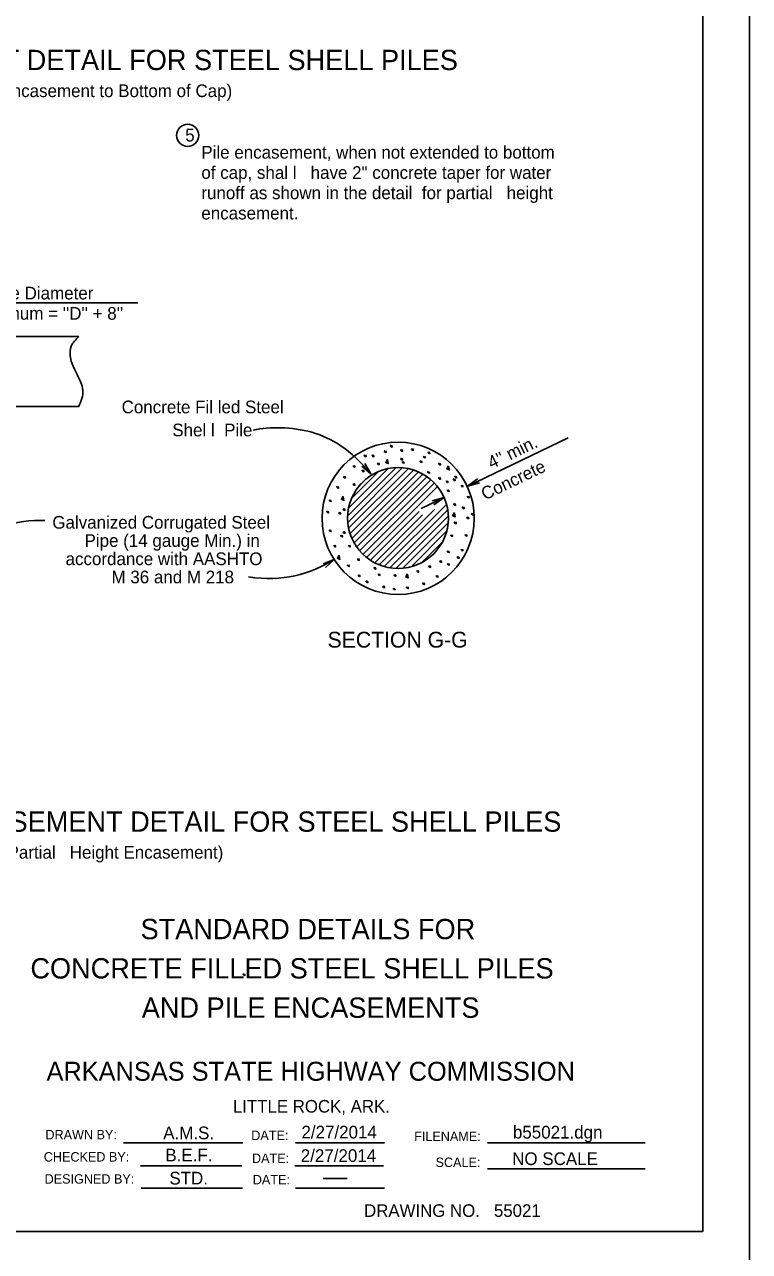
# Model space of a CAD drawing. Extents: x 1053 to 1311, y 5085 to 5337.
# Drawn here: x 1193.9 to 1232, y 5199.9 to 5264.4 of the extents above; entities that cross this region are included whole.
import ezdxf

# ---------------------------------------------------------------- set-up
doc = ezdxf.new("R2010")
doc.units = 0
for name, color, linetype in [('1', 7, 'Continuous'), ('2', 7, 'Continuous'), ('7', 7, 'Continuous'), ('9', 7, 'Continuous'), ('B_No_Plot', 7, 'Continuous')]:
    doc.layers.add(name, color=color, linetype=linetype)

msp = doc.modelspace()

# ---------------------------------------------------------------- linework, layer by layer
at = {"layer": '1'}
for p, q in [((1229.529, 5200.971), (1229.529, 5310.539)), ((1183.514, 5248.033), (1196.697, 5248.033)), ((1183.514, 5244.36), (1196.697, 5244.36)), ((1217.131, 5240.157), (1222.442, 5242.71)), ((1210.846, 5238.615), (1213.369, 5241.138)), ((1210.852, 5238.267), (1213.717, 5241.133)), ((1210.893, 5239.016), (1212.969, 5241.091)), ((1210.895, 5237.957), (1214.027, 5241.089)), ((1210.969, 5237.677), (1214.308, 5241.016)), ((1211.053, 5239.529), (1212.456, 5240.932)), ((1211.066, 5237.421), (1214.563, 5240.918)), ((1211.185, 5237.186), (1214.798, 5240.799)), ((1211.31, 5236.957), (1215.014, 5240.662)), ((1211.503, 5236.797), (1215.213, 5240.507)), ((1211.672, 5236.612), (1215.395, 5240.335)), ((1211.838, 5236.425), (1215.56, 5240.147)), ((1217.145, 5240.171), (1217.679, 5240.555)), ((1217.145, 5240.171), (1217.778, 5240.349)), ((1214.702, 5238.989), (1215.914, 5239.572)), ((1215.914, 5239.572), (1215.281, 5239.394)), ((1215.914, 5239.572), (1215.38, 5239.188)), ((1212.043, 5236.276), (1214.601, 5238.835)), ((1212.507, 5236.034), (1215.409, 5238.936)), ((1212.771, 5235.944), (1216.041, 5239.213)), ((1213.06, 5235.88), (1216.105, 5238.924)), ((1212.265, 5236.145), (1214.778, 5238.658)), ((1213.381, 5235.847), (1216.138, 5238.604)), ((1213.742, 5235.854), (1216.131, 5238.243)), ((1214.176, 5235.934), (1216.05, 5237.809)), ((1214.763, 5236.168), (1215.816, 5237.221)), ((1199.054, 5205.627), (1205.326, 5205.627)), ((1208.105, 5205.627), (1212.772, 5205.627)), ((1218.206, 5205.627), (1226.484, 5205.627)), ((1199.94, 5204.422), (1205.273, 5204.422)), ((1208.062, 5204.422), (1212.729, 5204.422)), ((1218.206, 5204.257), (1226.484, 5204.257)), ((1199.977, 5203.254), (1205.31, 5203.254)), ((1208.105, 5203.254), (1212.772, 5203.254)), ((1229.529, 5200.971), (1060.921, 5200.971))]:
    msp.add_line(p, q, dxfattribs=at)
for points in [[(1212.939, 5241.584), (1212.845, 5241.415), (1212.977, 5241.358), (1212.939, 5241.546)], [(1211.753, 5241.359), (1212.07, 5240.821), (1211.588, 5241.218)], [(1212.987, 5241.096), (1212.975, 5241.082)], [(1214.017, 5241.092), (1214.009, 5241.082)], [(1214.806, 5240.796), (1214.784, 5240.77)], [(1216.155, 5241.245), (1216.061, 5241.076), (1216.193, 5241.02), (1216.155, 5241.208)], [(1211.424, 5240.146), (1211.353, 5240.06)], [(1211.556, 5240.305), (1211.424, 5240.146)], [(1215.563, 5240.149), (1215.56, 5240.146)], [(1210.607, 5239.647), (1210.513, 5239.477), (1210.645, 5239.421), (1210.607, 5239.609)], [(1210.907, 5238.898), (1210.863, 5238.845)], [(1216.107, 5238.934), (1216.077, 5238.898)], [(1216.456, 5238.782), (1216.362, 5238.612), (1216.494, 5238.556), (1216.456, 5238.744)], [(1210.907, 5237.962), (1210.896, 5237.949)], [(1216.094, 5237.983), (1216.077, 5237.962)], [(1209.558, 5236.082), (1210.139, 5236.314), (1209.672, 5235.898)], [(1210.4, 5236.544), (1210.306, 5236.374), (1210.438, 5236.318), (1210.4, 5236.506)], [(1215.043, 5236.402), (1214.928, 5236.264)], [(1212.458, 5236.09), (1212.434, 5236.061)], [(1214.526, 5236.09), (1214.476, 5236.03)], [(1213.992, 5235.565), (1213.898, 5235.396), (1214.03, 5235.34), (1213.992, 5235.528)]]:
    msp.add_lwpolyline(points, dxfattribs=at)
for centre, radius in [((1202.432, 5258.619), 0.583), ((1213.497, 5238.478), 4.003), ((1213.492, 5238.493), 2.652)]:
    msp.add_circle(centre, radius, dxfattribs=at)
for points in [[(1196.697, 5248.033), (1196.306, 5247.53), (1196.25, 5247.027), (1196.334, 5246.664), (1196.529, 5246.217), (1196.808, 5245.63), (1196.92, 5245.211), (1196.697, 5244.36)], [(1213.127, 5242.318), (1213.09, 5242.28), (1213.184, 5242.224), (1213.146, 5242.318)], [(1213.673, 5242.092), (1213.635, 5242.054), (1213.729, 5241.998), (1213.692, 5242.092)], [(1214.237, 5242.148), (1214.199, 5242.111), (1214.293, 5242.054), (1214.256, 5242.148)], [(1211.754, 5241.81), (1211.717, 5241.772), (1211.811, 5241.716), (1211.773, 5241.81)], [(1212.168, 5241.81), (1212.131, 5241.772), (1212.225, 5241.716), (1212.187, 5241.81)], [(1212.808, 5242.035), (1212.77, 5241.998), (1212.864, 5241.941), (1212.826, 5242.035)], [(1213.673, 5241.64), (1213.635, 5241.603), (1213.729, 5241.546), (1213.692, 5241.64)], [(1213.748, 5241.471), (1213.71, 5241.434), (1213.804, 5241.377), (1213.767, 5241.471)], [(1214.688, 5241.509), (1214.651, 5241.471), (1214.745, 5241.415), (1214.707, 5241.509)], [(1214.858, 5241.753), (1214.82, 5241.716), (1214.914, 5241.659), (1214.876, 5241.753)], [(1215.102, 5241.979), (1215.065, 5241.941), (1215.159, 5241.885), (1215.121, 5241.979)], [(1211.171, 5241.264), (1211.134, 5241.227), (1211.228, 5241.17), (1211.19, 5241.264)], [(1211.641, 5241.02), (1211.604, 5240.982), (1211.698, 5240.926), (1211.66, 5241.02)], [(1212.45, 5241.396), (1212.413, 5241.358), (1212.507, 5241.302), (1212.469, 5241.396)], [(1215.083, 5240.945), (1215.046, 5240.907), (1215.14, 5240.851), (1215.102, 5240.945)], [(1215.666, 5241.377), (1215.629, 5241.34), (1215.723, 5241.283), (1215.685, 5241.377)], [(1210.306, 5240.155), (1210.269, 5240.117), (1210.363, 5240.061), (1210.325, 5240.155)], [(1210.666, 5240.693), (1210.628, 5240.655), (1210.722, 5240.599), (1210.685, 5240.693)], [(1211.171, 5240.305), (1211.134, 5240.267), (1211.228, 5240.211), (1211.19, 5240.305)], [(1215.666, 5240.625), (1215.629, 5240.587), (1215.723, 5240.531), (1215.685, 5240.625)], [(1216.061, 5240.456), (1216.024, 5240.418), (1216.118, 5240.362), (1216.08, 5240.456)], [(1216.437, 5240.55), (1216.4, 5240.512), (1216.494, 5240.456), (1216.456, 5240.55)], [(1216.513, 5240.7), (1216.475, 5240.662), (1216.569, 5240.606), (1216.532, 5240.7)], [(1216.851, 5240.23), (1216.814, 5240.192), (1216.908, 5240.136), (1216.87, 5240.23)], [(1216.118, 5239.985), (1216.08, 5239.948), (1216.174, 5239.891), (1216.137, 5239.985)], [(1217.171, 5239.647), (1217.133, 5239.609), (1217.227, 5239.553), (1217.19, 5239.647)], [(1209.779, 5238.857), (1209.742, 5238.819), (1209.836, 5238.763), (1209.798, 5238.857)], [(1209.911, 5239.459), (1209.874, 5239.421), (1209.968, 5239.365), (1209.93, 5239.459)], [(1210.645, 5238.989), (1210.607, 5238.951), (1210.701, 5238.895), (1210.663, 5238.989)], [(1216.456, 5239.252), (1216.419, 5239.214), (1216.513, 5239.158), (1216.475, 5239.252)], [(1216.913, 5239.076), (1216.876, 5239.038), (1216.97, 5238.982), (1216.932, 5239.076)], [(1210.419, 5238.8), (1210.381, 5238.763), (1210.475, 5238.706), (1210.438, 5238.8)], [(1216.494, 5238.293), (1216.456, 5238.255), (1216.55, 5238.199), (1216.513, 5238.293)], [(1217.152, 5238.556), (1217.115, 5238.518), (1217.209, 5238.462), (1217.171, 5238.556)], [(1217.397, 5238.744), (1217.359, 5238.706), (1217.453, 5238.65), (1217.416, 5238.744)], [(1209.911, 5237.879), (1209.874, 5237.841), (1209.968, 5237.785), (1209.93, 5237.879)], [(1210.513, 5237.597), (1210.475, 5237.559), (1210.569, 5237.503), (1210.532, 5237.597)], [(1210.645, 5237.785), (1210.607, 5237.747), (1210.701, 5237.691), (1210.663, 5237.785)], [(1216.306, 5237.616), (1216.268, 5237.578), (1216.362, 5237.522), (1216.325, 5237.616)], [(1217.058, 5237.634), (1217.021, 5237.597), (1217.115, 5237.54), (1217.077, 5237.634)], [(1210.156, 5237.07), (1210.118, 5237.033), (1210.212, 5236.976), (1210.174, 5237.07)], [(1210.927, 5237.07), (1210.889, 5237.033), (1210.983, 5236.976), (1210.946, 5237.07)], [(1211.399, 5236.359), (1211.361, 5236.322), (1211.455, 5236.265), (1211.418, 5236.359)], [(1215.73, 5236.259), (1215.693, 5236.222), (1215.787, 5236.165), (1215.749, 5236.259)], [(1216.118, 5236.769), (1216.08, 5236.732), (1216.174, 5236.675), (1216.137, 5236.769)], [(1216.644, 5236.468), (1216.607, 5236.431), (1216.701, 5236.374), (1216.663, 5236.468)], [(1216.851, 5236.863), (1216.814, 5236.826), (1216.908, 5236.769), (1216.87, 5236.863)], [(1210.87, 5236.036), (1210.833, 5235.998), (1210.927, 5235.942), (1210.889, 5236.036)], [(1212.262, 5235.904), (1212.225, 5235.866), (1212.319, 5235.81), (1212.281, 5235.904)], [(1214.519, 5235.735), (1214.482, 5235.697), (1214.576, 5235.641), (1214.538, 5235.735)], [(1215.147, 5235.993), (1215.11, 5235.955), (1215.204, 5235.899), (1215.166, 5235.993)], [(1216.13, 5236.109), (1216.093, 5236.072), (1216.187, 5236.015), (1216.149, 5236.109)], [(1211.435, 5235.509), (1211.397, 5235.471), (1211.491, 5235.415), (1211.453, 5235.509)], [(1211.848, 5235.189), (1211.811, 5235.152), (1211.905, 5235.095), (1211.867, 5235.189)], [(1212.488, 5235.565), (1212.45, 5235.528), (1212.544, 5235.471), (1212.507, 5235.565)], [(1213.315, 5235.528), (1213.278, 5235.49), (1213.372, 5235.434), (1213.334, 5235.528)], [(1214.824, 5235.089), (1214.786, 5235.052), (1214.88, 5234.995), (1214.843, 5235.089)], [(1215.532, 5235.476), (1215.495, 5235.438), (1215.589, 5235.382), (1215.551, 5235.476)], [(1212.732, 5234.926), (1212.695, 5234.888), (1212.789, 5234.832), (1212.751, 5234.926)], [(1213.278, 5234.813), (1213.24, 5234.776), (1213.334, 5234.719), (1213.297, 5234.813)], [(1213.974, 5234.878), (1213.936, 5234.841), (1214.03, 5234.784), (1213.992, 5234.878)], [(1205.378, 5214.524), (1205.341, 5214.486), (1205.435, 5214.43), (1205.397, 5214.524)]]:
    msp.add_spline(points, degree=3, dxfattribs=at)
at = {"layer": '2'}
msp.add_line((1199.814, 5249.81), (1190.359, 5249.81), dxfattribs=at)
at = {"layer": '7'}
msp.add_line((1209.553, 5203.762), (1210.817, 5203.762), dxfattribs=at)
for points in [[(1205.882, 5243.12), (1206.754, 5243.291), (1209.04, 5243.315), (1210.976, 5242.1), (1212.07, 5240.821)], [(1194.915, 5238.366), (1194.211, 5238.39), (1192.57, 5238.198), (1191.128, 5237.389), (1190.346, 5236.694)], [(1205.631, 5235.394), (1206.541, 5235.259), (1208.098, 5235.325), (1209.531, 5235.938), (1210.139, 5236.314)]]:
    msp.add_open_spline(points, degree=3, dxfattribs=at)
at = {"layer": 'B_No_Plot'}
msp.add_lwpolyline([(1053.308, 5312.654), (1231.974, 5312.654), (1231.974, 5198.862), (1053.308, 5198.862)], close=True, dxfattribs=at)

# ---------------------------------------------------------------- texts
at = {"layer": '1'}
for s, height, p in [('5', 0.667, (1202.299, 5258.301)), ('Concrete Fil led Steel', 0.66667, (1198.956, 5244.003)), ('Shel l  Pile', 0.66667, (1201.622, 5242.791)), ('Galvanized Corrugated Steel', 0.66667, (1195.312, 5237.934)), ('Pipe (14 gauge Min.) in', 0.66667, (1197.007, 5236.976)), ('accordance with AASHTO ', 0.66667, (1196.008, 5236.017)), ('M 36 and M 218', 0.66667, (1198.424, 5235.059)), ('SECTION G-G', 0.83325, (1209.786, 5231.678)), ('ARKANSAS STATE HIGHWAY COMMISSION', 0.99734, (1195.006, 5208.896)), ('LITTLE ROCK, ARK.', 0.66134, (1204.809, 5207.222)), ('b55021.dgn', 0.6667, (1219.535, 5205.858)), ('DRAWN BY:', 0.496, (1194.948, 5205.814)), ('DATE:', 0.496, (1205.774, 5205.776)), ('FILENAME:', 0.496, (1214.34, 5205.728)), ('CHECKED BY:', 0.496, (1194.862, 5204.646)), ('DATE:', 0.496, (1205.812, 5204.571)), ('SCALE:', 0.496, (1215.465, 5204.358)), ('NO SCALE', 0.6667, (1219.495, 5204.462)), ('DESIGNED BY:', 0.496, (1194.905, 5203.483)), ('DATE:', 0.496, (1205.854, 5203.446)), ('DRAWING NO.   55021 ', 0.66134, (1211.707, 5201.736))]:
    msp.add_text(s, height=height, dxfattribs=at).set_placement(p)
for s, rotation, p in [("4'' min.", 25.67294, (1218.407, 5241.055)), ('Concrete', 25.67262, (1218.062, 5239.413))]:
    msp.add_text(s, height=0.6667, rotation=rotation, dxfattribs=at).set_placement(p)
at = {"layer": '7'}
for s, height, p in [('PILE ENCASEMENT DETAIL FOR STEEL SHELL PILES', 1.067, (1180.167, 5262.054)), ('(Shown with Encasement to Bottom of Cap)', 0.66667, (1187.479, 5260.634)), ('Pile encasement, when not extended to bottom', 0.66667, (1203.149, 5257.398)), ('of cap, shal l   have 2" concrete taper for water', 0.66667, (1203.149, 5256.332)), ('runoff as shown in the detail  for partial   height', 0.66667, (1203.149, 5255.265)), ('encasement.', 0.66667, (1203.149, 5254.198)), ('ALTERNATE PILE ENCASEMENT DETAIL FOR STEEL SHELL PILES', 1.067, (1176.807, 5221.993)), ('(Shown with Partial   Height Encasement)', 0.66658, (1187.856, 5220.579)), ('STANDARD DETAILS FOR', 1.067, (1199.952, 5216.342)), ('CONCRETE FILLED STEEL SHELL PILES', 1.067, (1194.159, 5214.275)), ('AND PILE ENCASEMENTS', 1.067, (1200.015, 5212.208)), ('2/27/2014', 0.6666, (1208.413, 5205.86)), ('A.M.S.', 0.6667, (1201.143, 5205.821)), ('B.E.F.', 0.6666, (1201.256, 5204.656)), ('2/27/2014', 0.6666, (1208.377, 5204.625)), ('STD.', 0.6667, (1201.468, 5203.439))]:
    msp.add_text(s, height=height, dxfattribs=at).set_placement(p)
at = {"layer": '9'}
for s, p in [('Inside Diameter', (1191.228, 5249.991)), ("Minimum = ''D'' + 8''", (1191.228, 5248.925))]:
    msp.add_text(s, height=0.66667, dxfattribs=at).set_placement(p)

doc.saveas('drawing.dxf')
